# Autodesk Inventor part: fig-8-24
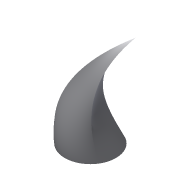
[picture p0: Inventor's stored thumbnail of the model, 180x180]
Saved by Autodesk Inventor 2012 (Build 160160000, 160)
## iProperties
Shininess: 77.0
Angle Display Precision: 2
Document Length Units: 11269
Document Angle Units: 11279
Document Time Units: 11290
Document Mass Units: 11283
Document Length Units Precision: 3
Document Angle Units Precision: 2
Created: 2001-12
Part Number: fig-8-24
Document SubType Name: Modeling
Designer: CADSoft
Density: 1 g/cm^3
Material: Default
Density: 0.0
Volumn: 0.0
Area: 0.0
PropertySet Name: Model Information
Control State: 0
Master: False
Checked Out: False
Author: CADSoft
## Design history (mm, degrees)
workplane "Work Plane3"
workplane "Work Plane4"
sketch "Sketch12"
  geometry: L1 (0, 10.598)-(9.178, -5.299); L2 (9.178, -5.299)-(-9.178, -5.299); L3 (-9.178, -5.299)-(0, 10.598); 1 further point
  constraints: 6 end point, 5 other
workplane "Work Plane5"
loft "Loft5" dims "d57" = 0, "d58" = 90 deg, "d59" = 0, "d60" = 90 deg, "d61" = 0, "d62" = 90 deg
body "Solid1"
sketch "Sketch1"
  geometry: C1 r 19.387 at (0, 0); 1 further point
  constraints: 1 centre point, 1 coincident, 1 other
sketch "Sketch2"
  geometry: 1 further point
